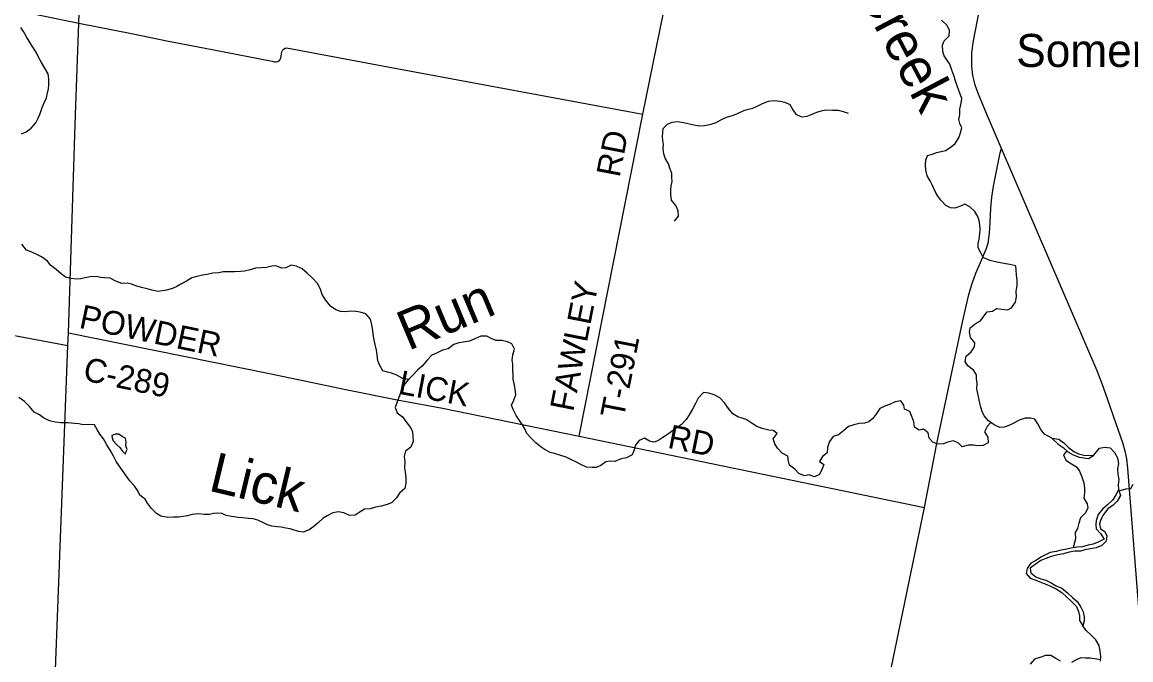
# Model space of a CAD drawing. Extents: x 0 to 34, y 0 to 22.
# Drawn here: x 5.122 to 6.445, y 17.405 to 18.167 of the extents above; entities that cross this region are included whole.
import ezdxf

# ---------------------------------------------------------------- set-up
doc = ezdxf.new("R2010")
doc.units = 0
for name, color, linetype in [('GM_X_County_Road', 7, 'Continuous'), ('GM_X_County_Road_Text', 7, 'Continuous'), ('GM_X_Minor_Lake', 7, 'Continuous'), ('GM_X_Minor_River', 7, 'Continuous'), ('GM_X_Minor_River_Text', 7, 'Continuous'), ('GM_X_State_Route', 7, 'Continuous'), ('GM_X_Township_Road', 7, 'Continuous'), ('GM_X_Township_Road_Text', 7, 'Continuous'), ('GM_X_Unincorporated_Text', 7, 'Continuous')]:
    doc.layers.add(name, color=color, linetype=linetype)

msp = doc.modelspace()

# ---------------------------------------------------------------- linework, layer by layer
at = {"layer": 'GM_X_County_Road'}
for points in [[(6.1307, 17.258), (6.1985, 17.587), (6.2136, 17.6635), (6.2224, 17.7072), (6.2442, 17.8087), (6.2516, 17.8417), (6.2554, 17.8549), (6.2601, 17.8673), (6.2642, 17.8772), (6.2722, 17.8957), (6.2747, 17.903), (6.2764, 17.9148), (6.2769, 17.9275), (6.2777, 17.9448), (6.2789, 17.9581), (6.2811, 17.9712), (6.2889, 18.0109), (6.2907, 18.0162)], [(4.2845, 17.9738), (4.3365, 17.9544), (4.3804, 17.9434), (4.4713, 17.9204), (4.5061, 17.9115), (4.5154, 17.9092), (4.5321, 17.9065), (4.5787, 17.8994), (4.6179, 17.894), (4.8287, 17.8794), (4.8392, 17.8777), (4.8453, 17.8759), (4.8506, 17.8734), (4.8585, 17.8684), (4.8976, 17.8393), (4.9051, 17.8341), (4.9104, 17.8318), (4.9166, 17.8299), (4.9228, 17.8284), (4.9275, 17.8274), (5.1759, 17.7808)], [(5.1767, 17.7957), (5.4168, 17.7471), (5.5081, 17.7281), (5.5693, 17.7158), (5.6235, 17.706), (5.7864, 17.6723), (6.1985, 17.587)]]:
    msp.add_lwpolyline(points, dxfattribs=at)
at = {"layer": 'GM_X_Minor_Lake'}
for points in [[(5.2459, 17.654), (5.2467, 17.6563), (5.2452, 17.6607), (5.2458, 17.6653), (5.245, 17.6698), (5.2411, 17.6721), (5.2369, 17.6748), (5.2324, 17.6748), (5.2284, 17.6731)], [(5.2284, 17.6731), (5.2288, 17.6703), (5.2303, 17.6667), (5.2342, 17.6625), (5.2383, 17.6587), (5.241, 17.6547), (5.2449, 17.6509), (5.2459, 17.654)]]:
    msp.add_lwpolyline(points, dxfattribs=at)
at = {"layer": 'GM_X_Minor_River'}
for points in [[(5.1207, 18.0337), (5.1264, 18.036), (5.1325, 18.0405), (5.1378, 18.0469), (5.1407, 18.0522), (5.1432, 18.0579), (5.1455, 18.065), (5.1478, 18.0707), (5.1505, 18.0768), (5.1517, 18.0824), (5.1528, 18.0874), (5.1532, 18.0923), (5.1533, 18.0991), (5.1524, 18.1052), (5.1486, 18.112), (5.1445, 18.1187), (5.1415, 18.1244), (5.1381, 18.1313), (5.1335, 18.1383), (5.1301, 18.1444), (5.1267, 18.1495), (5.123, 18.156), (5.12, 18.1608)], [(6.2362, 18.0958), (6.2339, 18.1032), (6.2313, 18.1099), (6.2289, 18.1167), (6.2255, 18.122), (6.2222, 18.127), (6.2205, 18.1319), (6.2203, 18.1395), (6.2221, 18.1448), (6.2282, 18.1508), (6.2286, 18.1575), (6.2252, 18.1636), (6.219, 18.1693)], [(6.3508, 17.6698), (6.3419, 17.6746), (6.3374, 17.6803), (6.3341, 17.6871), (6.3303, 17.6926), (6.3251, 17.6938), (6.3188, 17.6937), (6.3118, 17.6914), (6.3054, 17.6879), (6.2987, 17.6847), (6.2938, 17.6832), (6.2885, 17.6829), (6.2819, 17.6861), (6.275, 17.6905), (6.2701, 17.6966), (6.2676, 17.7018), (6.266, 17.7069), (6.2647, 17.7118), (6.2636, 17.7177), (6.2623, 17.7234), (6.2612, 17.7286), (6.2614, 17.7358), (6.2609, 17.7411), (6.2609, 17.7458), (6.257, 17.7511), (6.2504, 17.7563), (6.2474, 17.7616), (6.2486, 17.7681), (6.2545, 17.7732), (6.2585, 17.7792), (6.2587, 17.7839), (6.2538, 17.7902), (6.2525, 17.7969), (6.2533, 17.802), (6.2592, 17.8067), (6.2655, 17.8101), (6.2695, 17.8159), (6.2733, 17.821), (6.2797, 17.8217), (6.2846, 17.8249), (6.2914, 17.8241), (6.2978, 17.8233), (6.3026, 17.8259), (6.3074, 17.8323), (6.3085, 17.8388), (6.3082, 17.8458), (6.3095, 17.8519), (6.3092, 17.8587), (6.3085, 17.8648), (6.3082, 17.8712), (6.3076, 17.876), (6.3006, 17.8775), (6.2957, 17.8781), (6.2893, 17.8795), (6.2833, 17.8807), (6.2765, 17.8824), (6.2689, 17.8859), (6.2663, 17.8906), (6.2628, 17.8973), (6.2628, 17.9024), (6.264, 17.9079), (6.2647, 17.9142), (6.265, 17.9198), (6.2648, 17.925), (6.2641, 17.9299), (6.2624, 17.9348), (6.2589, 17.9409), (6.2528, 17.9465), (6.2468, 17.9494), (6.2417, 17.9473), (6.2349, 17.9447), (6.2298, 17.9453), (6.2241, 17.9478), (6.2181, 17.9545), (6.2147, 17.9592), (6.2119, 17.964), (6.2084, 17.9718), (6.2056, 17.9775), (6.2018, 17.9836), (6.2004, 17.9904), (6.2, 17.9969), (6.2003, 18.002), (6.2022, 18.0077), (6.2084, 18.0093), (6.2132, 18.0114), (6.2185, 18.0125), (6.2238, 18.0138), (6.2306, 18.0181), (6.2353, 18.022), (6.2395, 18.0287), (6.2415, 18.0347), (6.2432, 18.041), (6.2408, 18.0459), (6.2395, 18.0508), (6.2408, 18.0567), (6.2409, 18.0633), (6.2426, 18.0703), (6.2432, 18.076), (6.2406, 18.0836), (6.238, 18.0899), (6.2362, 18.0958)], [(5.9003, 17.9292), (5.9052, 17.9354), (5.9045, 17.9415), (5.9019, 17.948), (5.8968, 17.9543), (5.8957, 17.9613), (5.896, 17.9662), (5.8962, 17.9713), (5.8973, 17.9766), (5.8972, 17.9814), (5.897, 17.9863), (5.8948, 17.9926), (5.8929, 17.9977), (5.889, 18.0045), (5.8875, 18.0097), (5.8866, 18.0159), (5.887, 18.0207), (5.8865, 18.0256), (5.8861, 18.0304), (5.8863, 18.0353), (5.8868, 18.0402), (5.8919, 18.0453), (5.8974, 18.0477), (5.904, 18.0484), (5.911, 18.0473), (5.9183, 18.0457), (5.9253, 18.0438), (5.9302, 18.0433), (5.9361, 18.0437), (5.9442, 18.045), (5.9501, 18.0472), (5.9571, 18.0511), (5.9622, 18.0534), (5.9706, 18.056), (5.9753, 18.058), (5.9829, 18.0614), (5.9884, 18.0631), (5.9937, 18.0644), (5.9988, 18.0666), (6.0052, 18.0698), (6.0124, 18.0728), (6.0194, 18.0733), (6.0262, 18.0725), (6.0321, 18.0715), (6.0381, 18.0688), (6.0417, 18.0625), (6.0449, 18.0572), (6.052, 18.0538), (6.0586, 18.0549), (6.0647, 18.0573), (6.0702, 18.0597), (6.0768, 18.0616), (6.0817, 18.0625), (6.0887, 18.0619), (6.0957, 18.0618), (6.1016, 18.0605), (6.1076, 18.0583)], [(5.5826, 17.7402), (5.575, 17.7418), (5.5688, 17.7452), (5.5626, 17.7475), (5.5577, 17.7489), (5.5522, 17.7506), (5.5485, 17.7567), (5.5463, 17.7624), (5.5455, 17.7694), (5.5446, 17.7751), (5.5428, 17.782), (5.5417, 17.7873), (5.5404, 17.7941), (5.5402, 17.7988), (5.539, 17.8055), (5.5373, 17.8121), (5.5318, 17.8184), (5.5249, 17.8207), (5.52, 17.8212), (5.5137, 17.8216), (5.5075, 17.821), (5.5014, 17.8213), (5.496, 17.8232), (5.4898, 17.8276), (5.4838, 17.8354), (5.4798, 17.8415), (5.4776, 17.848), (5.4742, 17.8546), (5.468, 17.8613), (5.4616, 17.8672), (5.4558, 17.8725), (5.449, 17.8754), (5.4426, 17.8768), (5.4364, 17.8736), (5.4314, 17.8731), (5.4245, 17.8761), (5.4194, 17.8754), (5.4131, 17.8741), (5.4069, 17.8734), (5.3999, 17.8731), (5.3936, 17.871), (5.387, 17.8696), (5.3821, 17.869), (5.3749, 17.8687), (5.3681, 17.8689), (5.3613, 17.8686), (5.3562, 17.8677), (5.3492, 17.8671), (5.3422, 17.8657), (5.3367, 17.8646), (5.3299, 17.8631), (5.324, 17.8614), (5.3176, 17.8577), (5.3111, 17.8541), (5.306, 17.8513), (5.3009, 17.8488), (5.2939, 17.847), (5.2841, 17.8452), (5.2763, 17.8469), (5.2708, 17.8483), (5.2642, 17.8502), (5.2573, 17.8522), (5.252, 17.8539), (5.2469, 17.8551), (5.2405, 17.8549), (5.2333, 17.8574), (5.2265, 17.8611), (5.2201, 17.8615), (5.2152, 17.8621), (5.2103, 17.8633), (5.2029, 17.8627), (5.1968, 17.8616), (5.1915, 17.8605), (5.1864, 17.86), (5.1796, 17.8608), (5.1734, 17.8624), (5.1683, 17.8662), (5.1623, 17.8717), (5.1555, 17.8765), (5.1518, 17.8815), (5.1448, 17.8868), (5.1399, 17.8891), (5.133, 17.8924), (5.1267, 17.8945), (5.1211, 17.9017)], [(5.8122, 17.6374), (5.8069, 17.6349), (5.8018, 17.6348), (5.7951, 17.6352), (5.7878, 17.639), (5.7823, 17.6415), (5.7772, 17.644), (5.771, 17.6473), (5.7646, 17.6494), (5.7571, 17.6516), (5.7518, 17.6527), (5.7459, 17.656), (5.7411, 17.6592), (5.7347, 17.6642), (5.7292, 17.6701), (5.7241, 17.6756), (5.7215, 17.681), (5.7187, 17.6859), (5.7154, 17.6911), (5.7114, 17.697), (5.7075, 17.7042), (5.7058, 17.7093), (5.7083, 17.7154), (5.7108, 17.7218), (5.7101, 17.7284), (5.7094, 17.7334), (5.7077, 17.7404), (5.7075, 17.7451), (5.7072, 17.7514), (5.7074, 17.7584), (5.7065, 17.7632), (5.7073, 17.7696), (5.7092, 17.7762), (5.7059, 17.7825), (5.701, 17.7852), (5.694, 17.7866), (5.6872, 17.7866), (5.6823, 17.7885), (5.6761, 17.792), (5.6691, 17.792), (5.6619, 17.7885), (5.6554, 17.786), (5.6479, 17.7847), (5.6428, 17.784), (5.6367, 17.7818), (5.6299, 17.7769), (5.6232, 17.775), (5.6162, 17.7717), (5.6105, 17.769), (5.6047, 17.7626), (5.5991, 17.7562), (5.594, 17.7515), (5.5875, 17.7449), (5.5826, 17.7402), (5.5782, 17.7347), (5.5742, 17.7281), (5.5721, 17.7204), (5.5694, 17.7132), (5.5667, 17.7065), (5.5693, 17.7003), (5.5755, 17.6953), (5.5795, 17.6898), (5.5853, 17.6829), (5.5875, 17.6776), (5.588, 17.6717), (5.5882, 17.6658), (5.5857, 17.6594), (5.5793, 17.6545), (5.5777, 17.6481), (5.5784, 17.6416), (5.578, 17.6346), (5.5787, 17.6297), (5.5794, 17.6227), (5.5796, 17.6162), (5.5784, 17.6098), (5.572, 17.6043), (5.5685, 17.5985), (5.5624, 17.5928), (5.5573, 17.5907), (5.5503, 17.5887), (5.5433, 17.5876), (5.5369, 17.5856), (5.5301, 17.585), (5.5238, 17.5813), (5.5189, 17.5781), (5.5123, 17.5776), (5.5057, 17.5808), (5.4993, 17.5818), (5.4925, 17.5807), (5.4858, 17.5773), (5.4807, 17.5745), (5.4752, 17.5692), (5.4697, 17.5645), (5.4642, 17.5606), (5.457, 17.5576), (5.4517, 17.5586), (5.4464, 17.5599), (5.4415, 17.5615), (5.4364, 17.5625), (5.4309, 17.5636), (5.4258, 17.5642)], [(6.2779, 17.6887), (6.2734, 17.6839), (6.2705, 17.6777), (6.2741, 17.671), (6.2748, 17.6644), (6.2687, 17.6612), (6.2621, 17.6607), (6.257, 17.6615), (6.2508, 17.6617), (6.2438, 17.6597), (6.2389, 17.6642), (6.233, 17.6666), (6.2266, 17.6651), (6.2215, 17.663), (6.2145, 17.6629), (6.2087, 17.6652), (6.2041, 17.67), (6.2032, 17.6762), (6.1974, 17.6806), (6.1925, 17.6795), (6.1866, 17.6833), (6.1859, 17.6896), (6.1835, 17.6959), (6.1813, 17.7018), (6.1749, 17.7047), (6.1739, 17.7094), (6.1704, 17.7147), (6.1638, 17.7135), (6.1571, 17.7103), (6.1515, 17.7084), (6.1452, 17.7054), (6.1406, 17.6984), (6.1372, 17.6933), (6.1321, 17.6894), (6.1271, 17.6877), (6.1207, 17.6876), (6.1145, 17.6859), (6.1078, 17.6841), (6.1021, 17.6788), (6.0961, 17.6741), (6.0896, 17.672), (6.0854, 17.666), (6.0829, 17.659), (6.0825, 17.6526), (6.0768, 17.6482), (6.0734, 17.6422), (6.0787, 17.6387), (6.076, 17.6325), (6.0735, 17.6266), (6.0674, 17.6238), (6.0612, 17.626), (6.0553, 17.6249), (6.0487, 17.6277), (6.044, 17.6329), (6.0376, 17.6377), (6.0363, 17.6424), (6.0354, 17.6485), (6.0287, 17.6521), (6.0234, 17.6579), (6.02, 17.663), (6.018, 17.6693), (6.0227, 17.6755), (6.0179, 17.6791), (6.0129, 17.6797), (6.005, 17.6817), (5.9986, 17.684), (5.9928, 17.6876), (5.9858, 17.6922), (5.9809, 17.694), (5.976, 17.6953), (5.9698, 17.699), (5.9649, 17.7056), (5.96, 17.7121), (5.9542, 17.718), (5.9478, 17.7217), (5.9414, 17.7238), (5.935, 17.7246), (5.9287, 17.7178), (5.9252, 17.7114), (5.9218, 17.7046), (5.9176, 17.698), (5.914, 17.6923), (5.9087, 17.6863), (5.9039, 17.6833), (5.8992, 17.6795), (5.892, 17.6742), (5.8863, 17.6709), (5.8802, 17.6669), (5.8755, 17.6651), (5.8706, 17.6662), (5.8645, 17.6699), (5.8579, 17.6672), (5.8535, 17.6612), (5.8523, 17.6559), (5.8499, 17.65), (5.843, 17.6463), (5.8366, 17.6452), (5.8292, 17.642), (5.8235, 17.6426), (5.8182, 17.6417), (5.8122, 17.6374)], [(5.4258, 17.5642), (5.4196, 17.565), (5.4145, 17.5664), (5.4087, 17.5691), (5.403, 17.5718), (5.3973, 17.5735), (5.3917, 17.5739), (5.3847, 17.5747), (5.3796, 17.5753), (5.3715, 17.5763), (5.3652, 17.5777), (5.3603, 17.5798), (5.3552, 17.5804), (5.3501, 17.5799), (5.345, 17.5789), (5.3392, 17.5788), (5.3316, 17.5796), (5.3244, 17.5787), (5.3189, 17.5772), (5.3138, 17.5763), (5.3082, 17.5754), (5.3023, 17.5754), (5.2955, 17.5753), (5.2872, 17.5768), (5.2821, 17.5801), (5.2759, 17.5858), (5.271, 17.5923), (5.2682, 17.5971), (5.2622, 17.602), (5.2598, 17.607), (5.2562, 17.6121), (5.2502, 17.6188), (5.247, 17.6235), (5.2421, 17.6302), (5.2373, 17.6371), (5.2339, 17.642), (5.2307, 17.6485), (5.2266, 17.6557), (5.2227, 17.6622), (5.2186, 17.669), (5.2143, 17.6749), (5.2114, 17.6797), (5.2079, 17.686), (5.2015, 17.6862), (5.1943, 17.6861), (5.1894, 17.6872), (5.1839, 17.6875), (5.176, 17.6881), (5.1678, 17.6883), (5.161, 17.6891), (5.1541, 17.6907), (5.1471, 17.6941), (5.1422, 17.6978), (5.136, 17.7009), (5.1302, 17.7077), (5.1243, 17.7136), (5.1176, 17.7186)], [(6.3508, 17.6698), (6.3583, 17.6629), (6.3642, 17.6589), (6.3698, 17.6537), (6.3762, 17.6499), (6.3832, 17.6472), (6.3945, 17.6458), (6.4004, 17.6491)], [(6.3508, 17.6698), (6.3591, 17.6686), (6.3649, 17.6645), (6.3706, 17.659), (6.3768, 17.654), (6.3826, 17.6513), (6.389, 17.6496), (6.4004, 17.6491)], [(6.3687, 17.6547), (6.3645, 17.65), (6.3673, 17.6437), (6.3742, 17.6393), (6.3803, 17.6356), (6.3838, 17.6305), (6.3866, 17.6238), (6.3889, 17.6166), (6.3898, 17.61), (6.3895, 17.6048), (6.3887, 17.5982), (6.3927, 17.5917), (6.3936, 17.5868), (6.3907, 17.5808), (6.385, 17.5747), (6.3829, 17.5685), (6.3812, 17.5621), (6.3787, 17.5571), (6.3788, 17.5496), (6.376, 17.5388)], [(6.4004, 17.6491), (6.4074, 17.6582), (6.4141, 17.6593), (6.4205, 17.6585), (6.4254, 17.653), (6.4289, 17.6465), (6.4302, 17.6395), (6.4292, 17.6332), (6.4295, 17.6268), (6.4306, 17.6205), (6.4298, 17.6143), (6.4304, 17.6086)], [(6.4309, 17.6069), (6.4391, 17.6095), (6.4449, 17.6098), (6.4478, 17.6149)], [(6.4304, 17.6086), (6.4275, 17.6025), (6.4231, 17.5959), (6.4172, 17.5904), (6.4113, 17.5852), (6.406, 17.5786), (6.4037, 17.5714), (6.4033, 17.5665), (6.4038, 17.5617), (6.4087, 17.556), (6.413, 17.5491), (6.4066, 17.546), (6.4001, 17.5433), (6.3939, 17.5421), (6.3873, 17.5402), (6.381, 17.5397), (6.3738, 17.5384), (6.3687, 17.5373), (6.3619, 17.5362), (6.3557, 17.5345), (6.3489, 17.5333), (6.3439, 17.531), (6.3377, 17.5278), (6.3324, 17.5243), (6.3257, 17.5205), (6.3213, 17.5141), (6.3202, 17.5084), (6.3247, 17.5027), (6.3317, 17.5004), (6.3384, 17.4975), (6.3449, 17.4952), (6.3498, 17.4929), (6.3558, 17.4898), (6.3627, 17.4854), (6.3684, 17.48), (6.3742, 17.4749), (6.3802, 17.4688), (6.3826, 17.4627), (6.3839, 17.4576), (6.3839, 17.4521), (6.3876, 17.4456)], [(6.4304, 17.6086), (6.4328, 17.6013), (6.4288, 17.5945), (6.424, 17.5898), (6.4174, 17.5857), (6.4124, 17.5787), (6.409, 17.5729), (6.4076, 17.5678), (6.4089, 17.5615), (6.414, 17.5586), (6.4164, 17.5531), (6.4157, 17.5467), (6.4103, 17.5416), (6.4035, 17.5388), (6.3967, 17.5379), (6.3901, 17.5366), (6.385, 17.5351), (6.3783, 17.5348), (6.3715, 17.5339), (6.3647, 17.5318), (6.3577, 17.5304), (6.3498, 17.5285), (6.3437, 17.5263), (6.3376, 17.5237), (6.3308, 17.519), (6.3247, 17.5146), (6.3255, 17.5089), (6.3315, 17.5042), (6.3375, 17.502), (6.3436, 17.5001), (6.35, 17.497), (6.356, 17.4934), (6.3626, 17.4909), (6.3694, 17.4853), (6.3752, 17.4796), (6.3812, 17.4745), (6.3855, 17.4682), (6.3879, 17.4623), (6.3894, 17.4564), (6.3892, 17.4516), (6.3876, 17.4456)], [(6.4089, 17.4034), (6.409, 17.4092), (6.4083, 17.4155), (6.407, 17.4221), (6.4032, 17.429), (6.3982, 17.4343), (6.3918, 17.4403), (6.3876, 17.4456)], [(6.3609, 17.4033), (6.3553, 17.4066), (6.3494, 17.4104), (6.343, 17.4104), (6.3362, 17.4078), (6.3301, 17.4058), (6.325, 17.4001)], [(6.409, 17.4051), (6.402, 17.4062), (6.3959, 17.4069), (6.391, 17.4071), (6.3853, 17.4073), (6.3806, 17.4054), (6.3742, 17.4021)]]:
    msp.add_lwpolyline(points, dxfattribs=at)
at = {"layer": 'GM_X_State_Route'}
for points in [[(5.1459, 16.9851), (5.1759, 17.7808), (5.1767, 17.7957), (5.1854, 18.0568), (5.1893, 18.1658), (5.2003, 18.4901), (5.2066, 18.668)], [(6.2552, 18.1144), (6.255, 18.1163), (6.2553, 18.1304), (6.2573, 18.1449), (6.2779, 18.2523), (6.2903, 18.3163)], [(6.493, 17.1792), (6.4834, 17.2222), (6.4761, 17.2552), (6.4722, 17.2734), (6.47, 17.2871), (6.4683, 17.302), (6.4533, 17.4821), (6.4414, 17.6341), (6.4402, 17.6452), (6.4384, 17.6546), (6.4354, 17.6644), (6.4276, 17.6869), (6.4176, 17.7158), (6.4109, 17.7349), (6.4049, 17.7506), (6.2907, 18.0162), (6.2726, 18.0581), (6.263, 18.0811), (6.2592, 18.0916), (6.2574, 18.0987), (6.2563, 18.1035), (6.2552, 18.1144)]]:
    msp.add_lwpolyline(points, dxfattribs=at)
at = {"layer": 'GM_X_Township_Road'}
for points in [[(5.7864, 17.6723), (5.8624, 18.057), (5.916, 18.3211)], [(4.6179, 17.894), (4.6395, 17.9893), (4.6542, 18.0547), (4.6728, 18.1375), (4.6924, 18.2264), (4.7021, 18.268), (4.7028, 18.272), (4.704, 18.2746), (4.7059, 18.276), (4.708, 18.2769), (4.711, 18.2773), (4.7136, 18.2769), (4.7188, 18.2751), (4.8124, 18.2448), (4.8238, 18.2414), (4.8319, 18.2392), (4.9665, 18.2115), (5.1042, 18.1833), (5.1893, 18.1658)], [(5.1893, 18.1658), (5.2522, 18.1534), (5.2943, 18.1447), (5.3504, 18.1341), (5.4201, 18.1203), (5.4229, 18.1197), (5.4248, 18.1197), (5.4267, 18.1201), (5.4283, 18.1209), (5.4297, 18.1224), (5.4304, 18.124), (5.4308, 18.1267), (5.4315, 18.1317), (5.4326, 18.1339), (5.4337, 18.135), (5.4355, 18.1361), (5.4373, 18.1363), (5.4391, 18.1361), (5.4413, 18.1356), (5.558, 18.1138), (5.8624, 18.057)]]:
    msp.add_lwpolyline(points, dxfattribs=at)

# ---------------------------------------------------------------- texts
at = {"layer": 'GM_X_County_Road_Text'}
for s, rotation, p in [('POWDER', 348.1788, (5.1884, 17.802)), ('C-289', 348.0406, (5.193, 17.7394)), ('LICK', 349.2946, (5.5694, 17.7233)), ('RD', 348.4957, (5.8909, 17.6586))]:
    msp.add_text(s, height=0.02841, rotation=rotation, dxfattribs=at).set_placement(p)
at = {"layer": 'GM_X_Minor_River_Text'}
for s, height, rotation, p in [('Creek', 0.04734, 297.8975, (6.1159, 18.2047)), ('Run', 0.04736, 22.703, (5.5823, 17.7741)), ('Lick', 0.04734, 346.4931, (5.3426, 17.6076))]:
    msp.add_text(s, height=height, rotation=rotation, dxfattribs=at).set_placement(p)
at = {"layer": 'GM_X_Township_Road_Text'}
for s, rotation, p in [('RD', 79.0755, (5.8347, 17.9807)), ('FAWLEY', 78.852, (5.7793, 17.7007)), ('T-291', 78.9665, (5.8395, 17.6924))]:
    msp.add_text(s, height=0.02841, rotation=rotation, dxfattribs=at).set_placement(p)
at = {"layer": 'GM_X_Unincorporated_Text'}
msp.add_text('Somersville', height=0.039489, rotation=0, dxfattribs=at).set_placement((6.3082, 18.1135))

doc.saveas('drawing.dxf')
